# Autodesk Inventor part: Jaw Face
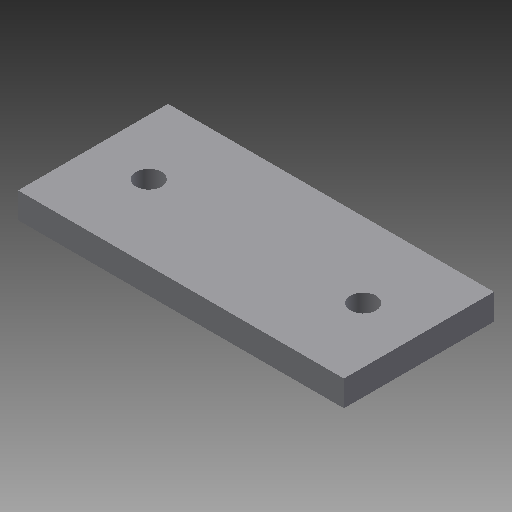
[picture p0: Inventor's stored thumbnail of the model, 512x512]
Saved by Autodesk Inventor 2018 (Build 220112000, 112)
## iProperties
Shininess: 77.0
Length Units: 11269
Angle Units: 11279
Time Units: 11290
Mass Units: 11283
Length Display Precision: 3
Angle Display Precision: 2
Compacted: True
Created: 2002-02
Part Number: Jaw Face
Document SubType Name: Modeling
Designer: ***
Density: 1 g/cm^3
Material: Generic
Appearance: Default
Density: 0.0
Volumn: 0.0
Area: 0.0
PropertySet Name: Model Information
Control State: 0
Master: False
Checked Out: False
Author: ***
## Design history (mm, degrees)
sketch "Sketch1"
  geometry: L1 (-79.661, -8.43)-(-3.661, -8.43); L2 (-3.661, -8.43)-(-3.661, -43.43); L3 (-3.661, -43.43)-(-79.661, -43.43); L4 (-79.661, -43.43)-(-79.661, -8.43); C1 r 3 at (-66.661, -25.93); C2 r 3 at (-16.661, -25.93)
  constraints: 8 end point, 2 centre point, 2 parallel, 1 equal radius, 1 horizontal, 1 perpendicular
  dimensions: "d0" = 76 distance of L2.end L3.end; "d1" = 6 diameter of C1; "d2" = 50 distance of C2.centre C1.centre; "d3" = 35 distance of L1.end L2.end; "d4" = 17.5 distance from line of L3 C2.centre; "d5" = 13 distance from line of L2 C2.centre; "d6" = 13 distance from line of L4 C1.centre
extrude "Extrusion1" new body sketch "Sketch1" stored distance "d7" = 6; taper "d8" = 0 deg
body "Solid1"
